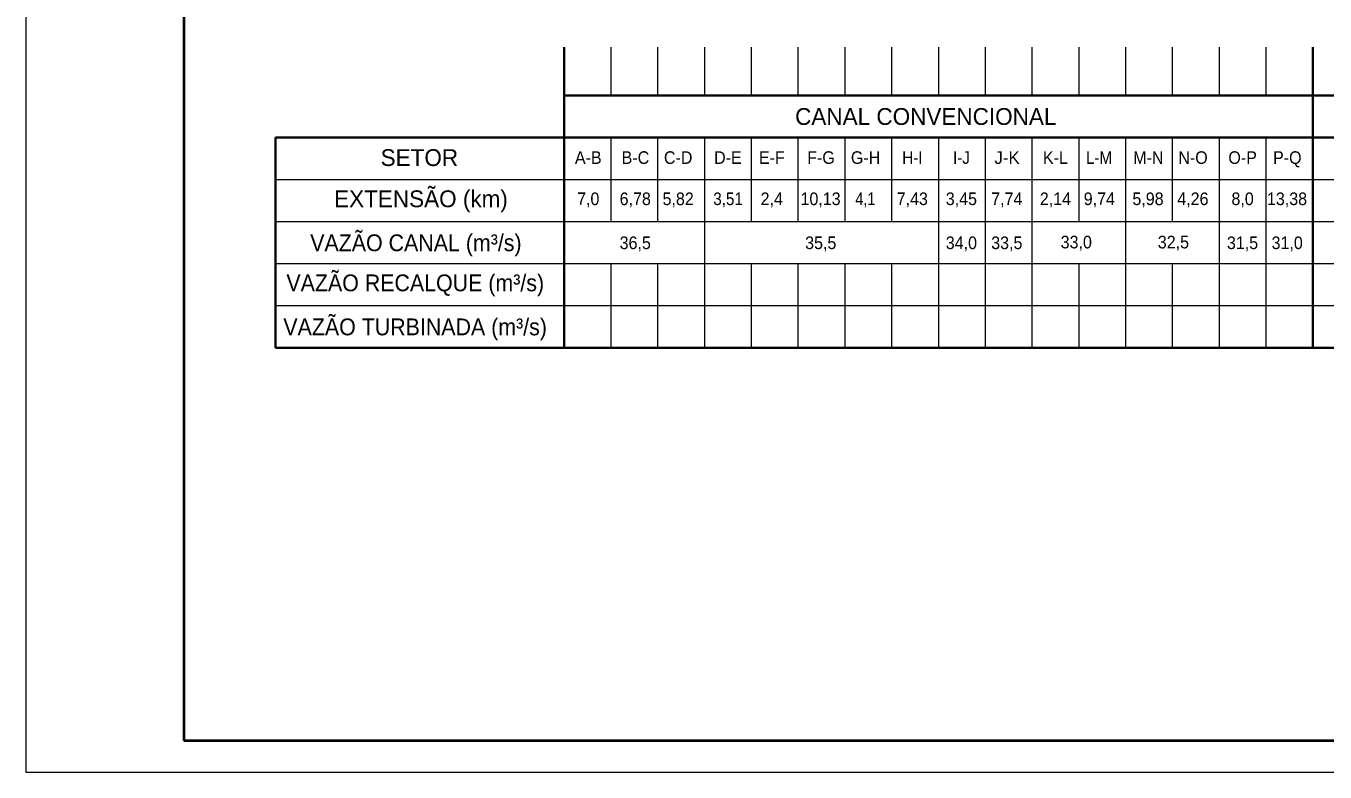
# Model space of a CAD drawing. Extents: x 8458 to 9360, y 19921 to 20366.
# Drawn here: x 8457.8 to 8766.6, y 19920.7 to 20098.1 of the extents above; entities that cross this region are included whole.
import ezdxf

# ---------------------------------------------------------------- set-up
doc = ezdxf.new("R2010")
doc.units = 0
doc.header["$LTSCALE"] = 1.2
doc.layers.add('1', color=7, linetype='Continuous', lineweight=40)
doc.layers.add('5', color=7, linetype='Continuous', lineweight=13)

msp = doc.modelspace()

# ---------------------------------------------------------------- linework, layer by layer
at = {"layer": '1'}
msp.add_line((8495.27, 19928.17), (9352.57, 19928.17), dxfattribs=at)
at = {"layer": '1', "lineweight": 13}
msp.add_lwpolyline([(8457.77, 19920.67), (9360.07, 19920.67), (9360.07, 20366.17), (8457.77, 20366.17)], close=True, dxfattribs=at)
at = {"layer": '1'}
msp.add_lwpolyline([(9352.57, 20358.67), (8495.27, 20358.67), (8495.27, 19928.17)], dxfattribs=at)
at = {"layer": '5', "lineweight": 35}
for p, q in [((8585.69, 20093.05), (8585.69, 20021.6)), ((8763.69, 20093.05), (8763.69, 20021.6)), ((8585.69, 20081.6), (9319.97, 20081.61)), ((8517.12, 20071.6), (8517.12, 20021.6)), ((8517.12, 20071.6), (8585.69, 20071.6)), ((8585.69, 20071.6), (9319.97, 20071.61)), ((8517.12, 20021.6), (9319.97, 20021.61))]:
    msp.add_line(p, q, dxfattribs=at)
at = {"layer": '5'}
for p, q in [((8596.81, 20093.05), (8596.81, 20081.6)), ((8607.94, 20093.05), (8607.94, 20081.6)), ((8619.07, 20093.05), (8619.07, 20081.6)), ((8630.19, 20093.05), (8630.19, 20081.6)), ((8641.31, 20093.05), (8641.31, 20081.6)), ((8652.44, 20093.05), (8652.44, 20081.6)), ((8663.57, 20093.05), (8663.57, 20081.6)), ((8674.69, 20093.05), (8674.69, 20081.6)), ((8685.81, 20093.05), (8685.81, 20081.6)), ((8696.94, 20093.05), (8696.94, 20081.6)), ((8708.07, 20093.05), (8708.07, 20081.6)), ((8719.19, 20093.05), (8719.19, 20081.6)), ((8730.31, 20093.05), (8730.31, 20081.6)), ((8741.44, 20093.05), (8741.44, 20081.6)), ((8752.57, 20093.05), (8752.57, 20081.6)), ((8596.81, 20071.6), (8596.81, 20051.6)), ((8607.94, 20071.6), (8607.94, 20051.6)), ((8619.07, 20071.6), (8619.07, 20021.6)), ((8630.19, 20071.6), (8630.19, 20051.6)), ((8641.31, 20071.6), (8641.31, 20051.6)), ((8652.44, 20071.6), (8652.44, 20051.6)), ((8663.57, 20071.6), (8663.57, 20051.6)), ((8674.69, 20071.6), (8674.69, 20021.6)), ((8685.81, 20071.6), (8685.81, 20021.6)), ((8696.94, 20071.6), (8696.94, 20021.6)), ((8708.07, 20071.6), (8708.07, 20051.6)), ((8719.19, 20071.6), (8719.19, 20021.6)), ((8730.31, 20071.6), (8730.31, 20051.6)), ((8741.44, 20071.6), (8741.44, 20021.6)), ((8752.57, 20071.6), (8752.57, 20021.6)), ((8517.12, 20061.6), (9319.97, 20061.61)), ((8517.12, 20051.6), (9319.97, 20051.61)), ((8517.12, 20041.6), (9319.97, 20041.61)), ((8535.69, 20041.6), (9319.97, 20041.61)), ((8596.81, 20041.6), (8596.81, 20021.6)), ((8607.94, 20041.6), (8607.94, 20021.6)), ((8630.19, 20041.6), (8630.19, 20021.6)), ((8641.31, 20041.6), (8641.31, 20021.6)), ((8652.44, 20041.6), (8652.44, 20021.6)), ((8663.57, 20041.6), (8663.57, 20021.6)), ((8708.07, 20041.6), (8708.07, 20021.6)), ((8730.31, 20041.6), (8730.31, 20021.6)), ((8517.12, 20031.6), (9319.97, 20031.61))]:
    msp.add_line(p, q, dxfattribs=at)

# ---------------------------------------------------------------- texts
for s, height, p in [('CANAL CONVENCIONAL', 4, (8640.64, 20074.59)), ('SETOR', 4, (8542.09, 20064.82)), ('J-K', 3, (8688.02, 20065.32)), ('EXTENSÃO (km)', 4, (8531.03, 20055.02))]:
    msp.add_text(s, height=height, dxfattribs=at).set_placement(p)
for s, height, width, p in [('A-B', 3, 0.95, (8588.28, 20065.32)), ('B-C', 3, 0.95, (8599.39, 20065.32)), ('C-D', 3, 0.95, (8609.45, 20065.32)), ('D-E', 3, 0.95, (8621.37, 20065.32)), ('E-F', 3, 0.95, (8632.03, 20065.32)), ('F-G', 3, 0.95, (8643.51, 20065.32)), ('G-H', 3, 0.95, (8653.9, 20065.32)), ('H-I', 3, 0.9, (8666.1, 20065.32)), ('I-J', 3, 0.9, (8678.18, 20065.32)), ('K-L', 3, 0.95, (8699.56, 20065.32)), ('L-M', 3, 0.9, (8709.78, 20065.32)), ('M-N', 3, 0.95, (8721.02, 20065.32)), ('N-O', 3, 0.95, (8731.74, 20065.32)), ('O-P', 3, 0.95, (8743.65, 20065.32)), ('P-Q', 3, 0.95, (8754.27, 20065.32)), ('7,0', 3, 0.95, (8588.8, 20055.52)), ('6,78', 3, 0.95, (8598.92, 20055.52)), ('5,82', 3, 0.95, (8609.12, 20055.52)), ('3,51', 3, 0.9, (8621.18, 20055.52)), ('2,4', 3, 0.95, (8632.44, 20055.52)), ('10,13', 3, 0.95, (8641.92, 20055.52)), ('4,1', 3, 0.85, (8654.96, 20055.52)), ('7,43', 3, 0.95, (8664.79, 20055.52)), ('3,45', 3, 0.95, (8676.46, 20055.52)), ('7,74', 3, 0.95, (8687.26, 20055.52)), ('2,14', 3, 0.95, (8698.82, 20055.52)), ('9,74', 3, 0.95, (8709.26, 20055.52)), ('5,98', 3, 0.95, (8720.83, 20055.52)), ('4,26', 3, 0.95, (8731.5, 20055.52)), ('8,0', 3, 0.95, (8744.38, 20055.52)), ('13,38', 3, 0.95, (8752.82, 20055.52)), ('VAZÃO CANAL (m³/s)', 4, 0.95, (8525.35, 20044.55)), ('36,5', 3, 0.95, (8598.92, 20045.05)), ('35,5', 3, 0.95, (8643.02, 20045.05)), ('34,0', 3, 0.95, (8676.46, 20045.05)), ('33,5', 3, 0.95, (8687.26, 20045.05)), ('33,0', 3, 0.95, (8703.78, 20045.22)), ('32,5', 3, 0.95, (8726.87, 20045.22)), ('31,5', 3, 0.95, (8743.3, 20045.05)), ('31,0', 3, 0.95, (8753.92, 20045.05)), ('VAZÃO RECALQUE (m³/s)', 4, 0.95, (8519.69, 20035.02)), ('VAZÃO TURBINADA (m³/s)', 4, 0.95, (8518.96, 20024.55))]:
    msp.add_text(s, height=height, dxfattribs=dict(at, width=width)).set_placement(p)

doc.saveas('drawing.dxf')
